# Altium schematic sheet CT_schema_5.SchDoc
size 258 x 163 mm
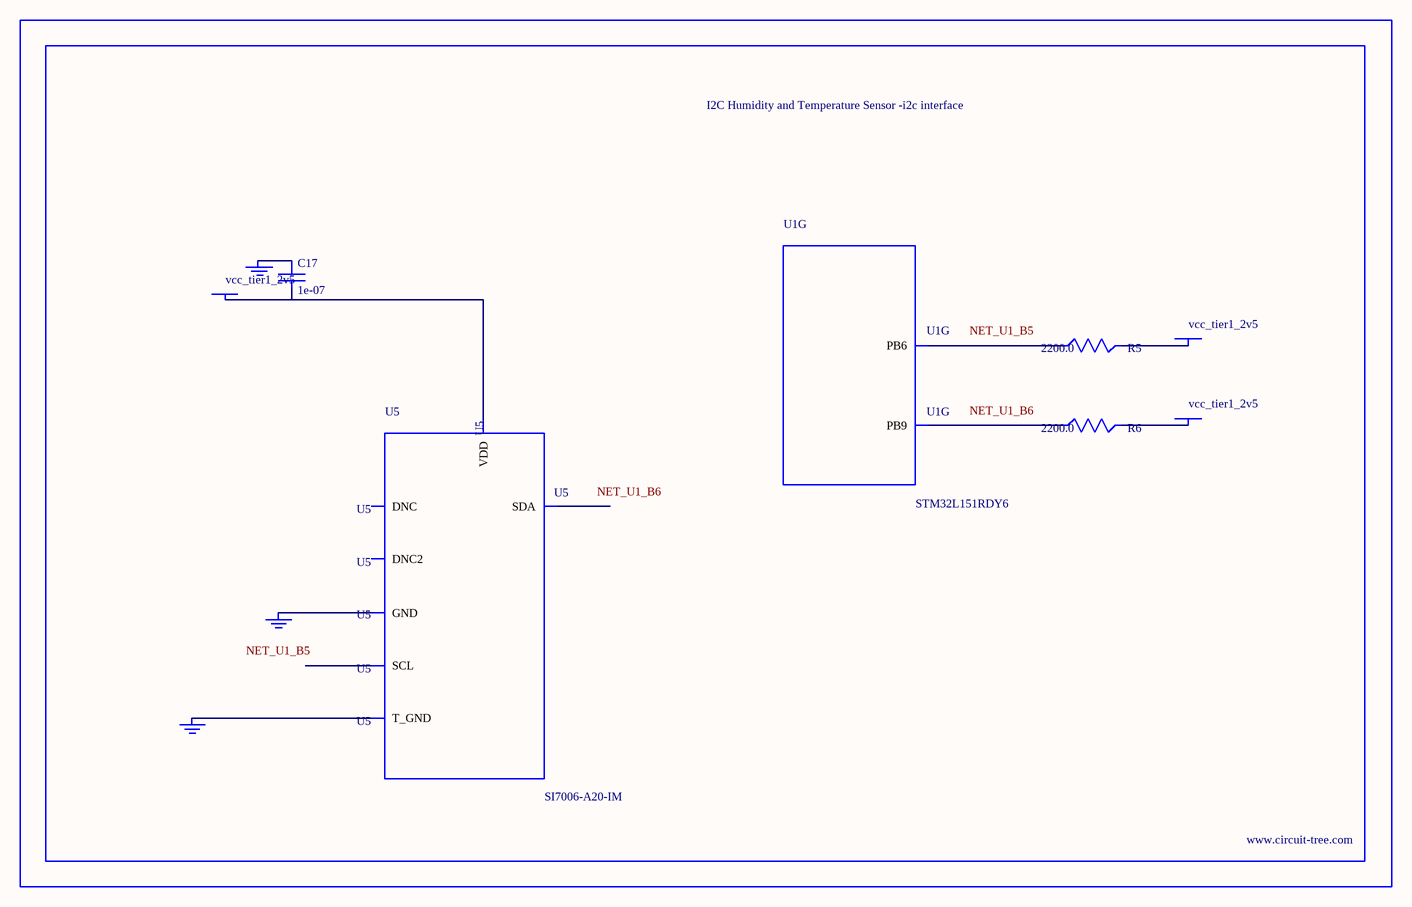
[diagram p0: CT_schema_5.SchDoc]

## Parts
BORDER4  (no value)
C17  1e-07  [C0402]
GND_INSTANCE_4_0  (no value)
GND_INSTANCE_4_1  (no value)
GND_INSTANCE_4_2  (no value)
POWER_INSTANCE_4_0  vcc_tier1_2v5
POWER_INSTANCE_4_1  vcc_tier1_2v5
POWER_INSTANCE_4_2  vcc_tier1_2v5
R5  2200.0  [R0603]
R6  2200.0  [R0603]
U1  STM32L151RDY6  [WLCSP64]  (part G of 8)
U5  SI7006-A20-IM  [DFN-6]

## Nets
NetC17_1: C17.1 GND_INSTANCE_4_0.0(GND)
NetC17_2: C17.2 POWER_INSTANCE_4_0.0(PWR) U5.5(VDD)
NetGND_INSTANCE_4_1_0: GND_INSTANCE_4_1.0(GND) U5.7(T_GND)
NetGND_INSTANCE_4_2_0: GND_INSTANCE_4_2.0(GND) U5.2(GND)
NetPOWER_INSTANCE_4_1_0: POWER_INSTANCE_4_1.0(PWR) R5.2
NetPOWER_INSTANCE_4_2_0: POWER_INSTANCE_4_2.0(PWR) R6.2
NetR5_1: R5.1 U1.B5(PB6)
NetR6_1: R6.1 U1.B6(PB9)

Not connected (* = marked no-connect by the designer): U5 1(SDA) 3(DNC) 4(DNC2) 6(SCL)

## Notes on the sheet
- Labels drawn without touching a wire or pin: NET_U1_B5, NET_U1_B6

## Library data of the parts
BORDER4 = BORDER_PAGE4
C17 = C0402C104K3RACTU
GND_INSTANCE_4_0-GND_INSTANCE_4_2 = GND
POWER_INSTANCE_4_0-POWER_INSTANCE_4_2 = PWR
R5 R6 = RC0603JR-072K2L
